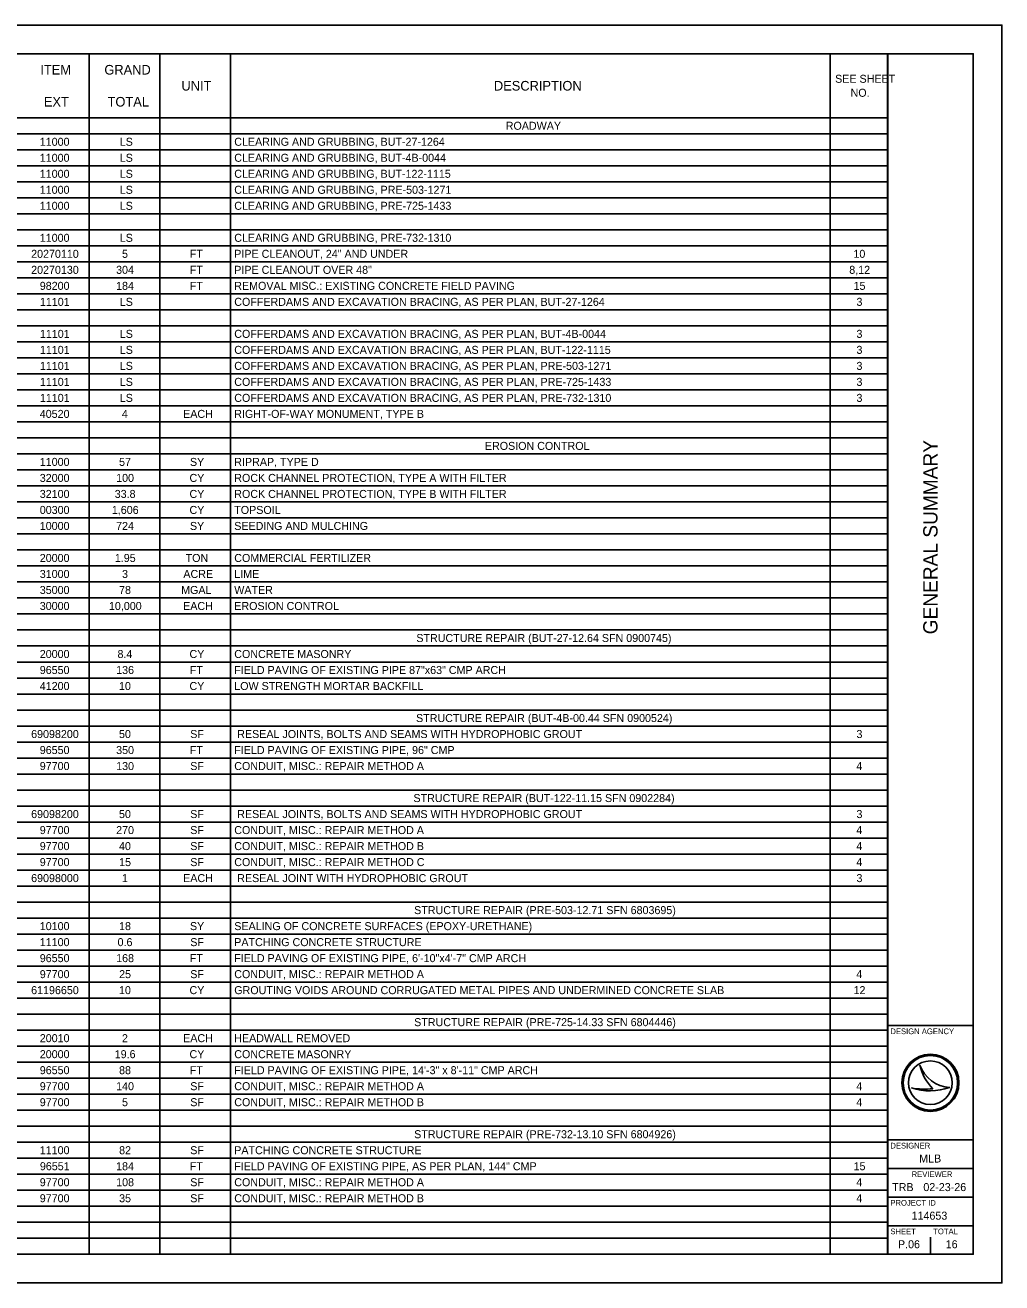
# Model space of a CAD drawing. Extents: x 0 to 34, y 0 to 22.
# Drawn here: x 16.92 to 34, y 0 to 22 of the extents above; entities that cross this region are included whole.
import ezdxf

# ---------------------------------------------------------------- set-up
doc = ezdxf.new("R2010")
doc.units = 0
for name, color, linetype in [('Default', 7, 'Continuous'), ('SH_Border', 7, 'Continuous'), ('SH_Cut_Line', 7, 'Continuous'), ('SH_Data', 7, 'Continuous')]:
    doc.layers.add(name, color=color, linetype=linetype)

msp = doc.modelspace()

# ---------------------------------------------------------------- linework, layer by layer
at = {"layer": 'Default'}
for p, q in [((1.5, 21.5), (32.004, 21.5)), ((18.036, 21.5), (18.036, 0.5)), ((19.272, 21.5), (19.272, 0.5)), ((20.507, 21.5), (20.507, 0.5)), ((30.999, 21.5), (30.999, 0.5)), ((32.004, 21.5), (32.004, 0.5)), ((1.5, 20.38), (32.004, 20.38)), ((1.5, 20.1), (32.004, 20.1)), ((1.5, 19.82), (32.004, 19.82)), ((1.5, 19.54), (32.004, 19.54)), ((1.5, 19.26), (32.004, 19.26)), ((1.5, 18.98), (32.004, 18.98)), ((1.5, 18.7), (32.004, 18.7)), ((1.5, 18.42), (32.004, 18.42)), ((1.5, 18.14), (32.004, 18.14)), ((1.5, 17.86), (32.004, 17.86)), ((1.5, 17.58), (32.004, 17.58)), ((1.5, 17.3), (32.004, 17.3)), ((1.5, 17.02), (32.004, 17.02)), ((1.5, 16.74), (32.004, 16.74)), ((1.5, 16.46), (32.004, 16.46)), ((1.5, 16.18), (32.004, 16.18)), ((1.5, 15.9), (32.004, 15.9)), ((1.5, 15.62), (32.004, 15.62)), ((1.5, 15.34), (32.004, 15.34)), ((1.5, 15.06), (32.004, 15.06)), ((1.5, 14.78), (32.004, 14.78)), ((1.5, 14.5), (32.004, 14.5)), ((1.5, 14.22), (32.004, 14.22)), ((1.5, 13.94), (32.004, 13.94)), ((1.5, 13.66), (32.004, 13.66)), ((1.5, 13.38), (32.004, 13.38)), ((1.5, 13.1), (32.004, 13.1)), ((1.5, 12.82), (32.004, 12.82)), ((1.5, 12.54), (32.004, 12.54)), ((1.5, 12.26), (32.004, 12.26)), ((1.5, 11.98), (32.004, 11.98)), ((1.5, 11.7), (32.004, 11.7)), ((1.5, 11.42), (32.004, 11.42)), ((1.5, 11.14), (32.004, 11.14)), ((1.5, 10.86), (32.004, 10.86)), ((1.5, 10.58), (32.004, 10.58)), ((1.5, 10.3), (32.004, 10.3)), ((1.5, 10.02), (32.004, 10.02)), ((1.5, 9.74), (32.004, 9.74)), ((1.5, 9.46), (32.004, 9.46)), ((1.5, 9.18), (32.004, 9.18)), ((1.5, 8.9), (32.004, 8.9)), ((1.5, 8.62), (32.004, 8.62)), ((1.5, 8.34), (32.004, 8.34)), ((1.5, 8.06), (32.004, 8.06)), ((1.5, 7.78), (32.004, 7.78)), ((1.5, 7.5), (32.004, 7.5)), ((1.5, 7.22), (32.004, 7.22)), ((1.5, 6.94), (32.004, 6.94)), ((1.5, 6.66), (32.004, 6.66)), ((1.5, 6.38), (32.004, 6.38)), ((1.5, 6.1), (32.004, 6.1)), ((1.5, 5.82), (32.004, 5.82)), ((1.5, 5.54), (32.004, 5.54)), ((1.5, 5.26), (32.004, 5.26)), ((1.5, 4.98), (32.004, 4.98)), ((1.5, 4.7), (32.004, 4.7)), ((1.5, 4.42), (32.004, 4.42)), ((1.5, 4.14), (32.004, 4.14)), ((1.5, 3.86), (32.004, 3.86)), ((1.5, 3.58), (32.004, 3.58)), ((1.5, 3.3), (32.004, 3.3)), ((1.5, 3.02), (32.004, 3.02)), ((1.5, 2.74), (32.004, 2.74)), ((1.5, 2.46), (32.004, 2.46)), ((1.5, 2.18), (32.004, 2.18)), ((1.5, 1.9), (32.004, 1.9)), ((1.5, 1.62), (32.004, 1.62)), ((1.5, 1.34), (32.004, 1.34)), ((1.5, 1.06), (32.004, 1.06)), ((1.5, 0.78), (32.004, 0.78)), ((1.5, 0.5), (32.004, 0.5))]:
    msp.add_line(p, q, dxfattribs=at)
at = {"layer": 'SH_Border'}
for p, q in [((32, 0.5), (32, 21.5)), ((32, 4.5), (33.5, 4.5)), ((32, 2.5), (33.5, 2.5)), ((32, 2), (33.5, 2)), ((32, 1.5), (33.5, 1.5)), ((32, 1), (33.5, 1))]:
    msp.add_line(p, q, dxfattribs=at)
msp.add_lwpolyline([(1.5, 21.5), (33.5, 21.5), (33.5, 0.5), (1.5, 0.5)], close=True, dxfattribs=at)
at = {"layer": 'SH_Cut_Line'}
msp.add_lwpolyline([(0, 0), (34, 0), (34, 22), (0, 22)], close=True, dxfattribs=at)
at = {"layer": 'SH_Data'}
for p, q in [((32.567, 3.81), (32.567, 3.81)), ((32.417, 3.41), (32.417, 3.41)), ((32.75, 3.5), (32.75, 3.5)), ((33.087, 3.419), (33.087, 3.419)), ((32.375, 0.675), (32.375, 0.675)), ((32.75, 0.5), (32.75, 0.8))]:
    msp.add_line(p, q, dxfattribs=at)
for radius in [0.5, 0.477, 0.477, 0.382]:
    msp.add_circle((32.75, 3.5), radius, dxfattribs=at)
for centre, radius, start, end in [((33.116, 3.998), 0.58, 198.9257, 198.9319), ((33.347, 3.97), 0.796, 191.6379, 191.6421), ((33.116, 3.998), 0.58, 198.9319, 267.1657), ((33.347, 3.97), 0.796, 191.6421, 226.0947), ((32.739, 4.37), 1.013, 251.4576, 290.0832), ((32.648, 4.654), 1.266, 259.4964, 259.4995), ((32.739, 4.37), 1.013, 251.4527, 251.4576), ((32.648, 4.654), 1.266, 259.4995, 276.6672)]:
    msp.add_arc(centre, radius, start, end, dxfattribs=at)

# ---------------------------------------------------------------- texts
at = {"layer": 'Default'}
for s, height, p in [('ITEM', 0.168, (17.181, 21.136)), ('GRAND', 0.168, (18.301, 21.136)), ('SEE SHEET ', 0.14, (31.084, 20.992)), ('UNIT', 0.168, (19.649, 20.856)), ('DESCRIPTION', 0.168, (25.115, 20.856)), ('EXT', 0.168, (17.242, 20.576)), ('TOTAL', 0.168, (18.357, 20.576)), ('NO.', 0.14, (31.354, 20.747)), ('ROADWAY', 0.14, (25.322, 20.17)), ('11000', 0.14, (17.171, 19.89)), ('LS', 0.14, (18.57, 19.89)), ('CLEARING AND GRUBBING, BUT-27-1264', 0.14, (20.573, 19.89)), ('11000', 0.14, (17.171, 19.61)), ('LS', 0.14, (18.57, 19.61)), ('CLEARING AND GRUBBING, BUT-4B-0044', 0.14, (20.573, 19.61)), ('11000', 0.14, (17.171, 19.33)), ('LS', 0.14, (18.57, 19.33)), ('CLEARING AND GRUBBING, BUT-122-1115', 0.14, (20.573, 19.33)), ('11000', 0.14, (17.171, 19.05)), ('LS', 0.14, (18.57, 19.05)), ('CLEARING AND GRUBBING, PRE-503-1271', 0.14, (20.573, 19.05)), ('11000', 0.14, (17.171, 18.77)), ('LS', 0.14, (18.57, 18.77)), ('CLEARING AND GRUBBING, PRE-725-1433', 0.14, (20.573, 18.77)), ('11000', 0.14, (17.171, 18.21)), ('LS', 0.14, (18.57, 18.21)), ('CLEARING AND GRUBBING, PRE-732-1310', 0.14, (20.573, 18.21)), ('20270110', 0.14, (17.02, 17.93)), ('5', 0.14, (18.61, 17.93)), ('FT', 0.14, (19.796, 17.93)), ('PIPE CLEANOUT, 24" AND UNDER', 0.14, (20.573, 17.93)), ('10', 0.14, (31.404, 17.93)), ('20270130', 0.14, (17.02, 17.65)), ('304', 0.14, (18.506, 17.65)), ('FT', 0.14, (19.796, 17.65)), ('PIPE CLEANOUT OVER 48"', 0.14, (20.573, 17.65)), ('8,12', 0.14, (31.331, 17.65)), ('98200', 0.14, (17.171, 17.37)), ('184', 0.14, (18.506, 17.37)), ('FT', 0.14, (19.796, 17.37)), ('REMOVAL MISC.: EXISTING CONCRETE FIELD PAVING', 0.14, (20.573, 17.37)), ('15', 0.14, (31.406, 17.37)), ('11101', 0.14, (17.173, 17.09)), ('LS', 0.14, (18.57, 17.09)), ('COFFERDAMS AND EXCAVATION BRACING, AS PER PLAN, BUT-27-1264', 0.14, (20.573, 17.09)), ('3', 0.14, (31.457, 17.09)), ('11101', 0.14, (17.173, 16.53)), ('LS', 0.14, (18.57, 16.53)), ('COFFERDAMS AND EXCAVATION BRACING, AS PER PLAN, BUT-4B-0044', 0.14, (20.573, 16.53)), ('3', 0.14, (31.457, 16.53)), ('11101', 0.14, (17.173, 16.25)), ('LS', 0.14, (18.57, 16.25)), ('COFFERDAMS AND EXCAVATION BRACING, AS PER PLAN, BUT-122-1115', 0.14, (20.573, 16.25)), ('3', 0.14, (31.457, 16.25)), ('11101', 0.14, (17.173, 15.97)), ('LS', 0.14, (18.57, 15.97)), ('COFFERDAMS AND EXCAVATION BRACING, AS PER PLAN, PRE-503-1271', 0.14, (20.573, 15.97)), ('3', 0.14, (31.457, 15.97)), ('11101', 0.14, (17.173, 15.69)), ('LS', 0.14, (18.57, 15.69)), ('COFFERDAMS AND EXCAVATION BRACING, AS PER PLAN, PRE-725-1433', 0.14, (20.573, 15.69)), ('3', 0.14, (31.457, 15.69)), ('11101', 0.14, (17.173, 15.41)), ('LS', 0.14, (18.57, 15.41)), ('COFFERDAMS AND EXCAVATION BRACING, AS PER PLAN, PRE-732-1310', 0.14, (20.573, 15.41)), ('3', 0.14, (31.457, 15.41)), ('40520', 0.14, (17.171, 15.13)), ('4', 0.14, (18.607, 15.13)), ('EACH', 0.14, (19.679, 15.13)), ('RIGHT-OF-WAY MONUMENT, TYPE B', 0.14, (20.573, 15.13)), ('EROSION CONTROL', 0.14, (24.957, 14.57)), ('11000', 0.14, (17.171, 14.29)), ('57', 0.14, (18.558, 14.29)), ('SY', 0.14, (19.798, 14.29)), ('RIPRAP, TYPE D', 0.14, (20.573, 14.29)), ('32000', 0.14, (17.171, 14.01)), ('100', 0.14, (18.507, 14.01)), ('CY', 0.14, (19.79, 14.01)), ('ROCK CHANNEL PROTECTION, TYPE A WITH FILTER', 0.14, (20.573, 14.01)), ('32100', 0.14, (17.171, 13.73)), ('33.8', 0.14, (18.482, 13.73)), ('CY', 0.14, (19.79, 13.73)), ('ROCK CHANNEL PROTECTION, TYPE B WITH FILTER', 0.14, (20.573, 13.73)), ('00300', 0.14, (17.171, 13.45)), ('1,606', 0.14, (18.432, 13.45)), ('CY', 0.14, (19.79, 13.45)), ('TOPSOIL', 0.14, (20.573, 13.45)), ('10000', 0.14, (17.171, 13.17)), ('724', 0.14, (18.506, 13.17)), ('SY', 0.14, (19.798, 13.17)), ('SEEDING AND MULCHING', 0.14, (20.573, 13.17)), ('20000', 0.14, (17.171, 12.61)), ('1.95', 0.14, (18.484, 12.61)), ('TON', 0.14, (19.722, 12.61)), ('COMMERCIAL FERTILIZER', 0.14, (20.573, 12.61)), ('31000', 0.14, (17.171, 12.33)), ('3', 0.14, (18.61, 12.33)), ('ACRE', 0.14, (19.683, 12.33)), ('LIME', 0.14, (20.573, 12.33)), ('35000', 0.14, (17.171, 12.05)), ('78', 0.14, (18.558, 12.05)), ('MGAL', 0.14, (19.644, 12.05)), ('WATER', 0.14, (20.573, 12.05)), ('30000', 0.14, (17.171, 11.77)), ('10,000', 0.14, (18.381, 11.77)), ('EACH', 0.14, (19.679, 11.77)), ('EROSION CONTROL', 0.14, (20.573, 11.77)), ('STRUCTURE REPAIR (BUT-27-12.64 SFN 0900745)', 0.14, (23.758, 11.21)), ('20000', 0.14, (17.171, 10.93)), ('8.4', 0.14, (18.531, 10.93)), ('CY', 0.14, (19.79, 10.93)), ('CONCRETE MASONRY', 0.14, (20.573, 10.93)), ('96550', 0.14, (17.171, 10.65)), ('136', 0.14, (18.507, 10.65)), ('FT', 0.14, (19.796, 10.65)), ('FIELD PAVING OF EXISTING PIPE 87"x63" CMP ARCH', 0.14, (20.573, 10.65)), ('41200', 0.14, (17.171, 10.37)), ('10', 0.14, (18.557, 10.37)), ('CY', 0.14, (19.79, 10.37)), ('LOW STRENGTH MORTAR BACKFILL', 0.14, (20.573, 10.37)), ('STRUCTURE REPAIR (BUT-4B-00.44 SFN 0900524)', 0.14, (23.753, 9.81)), ('69098200', 0.14, (17.02, 9.53)), ('50', 0.14, (18.557, 9.53)), ('SF', 0.14, (19.803, 9.53)), (' RESEAL JOINTS, BOLTS AND SEAMS WITH HYDROPHOBIC GROUT', 0.14, (20.573, 9.53)), ('3', 0.14, (31.457, 9.53)), ('96550', 0.14, (17.171, 9.25)), ('350', 0.14, (18.507, 9.25)), ('FT', 0.14, (19.796, 9.25)), ('FIELD PAVING OF EXISTING PIPE, 96" CMP', 0.14, (20.573, 9.25)), ('97700', 0.14, (17.171, 8.97)), ('130', 0.14, (18.507, 8.97)), ('SF', 0.14, (19.803, 8.97)), ('CONDUIT, MISC.: REPAIR METHOD A', 0.14, (20.573, 8.97)), ('4', 0.14, (31.454, 8.97)), ('STRUCTURE REPAIR (BUT-122-11.15 SFN 0902284)', 0.14, (23.708, 8.41)), ('69098200', 0.14, (17.02, 8.13)), ('50', 0.14, (18.557, 8.13)), ('SF', 0.14, (19.803, 8.13)), (' RESEAL JOINTS, BOLTS AND SEAMS WITH HYDROPHOBIC GROUT', 0.14, (20.573, 8.13)), ('3', 0.14, (31.457, 8.13)), ('97700', 0.14, (17.171, 7.85)), ('270', 0.14, (18.507, 7.85)), ('SF', 0.14, (19.803, 7.85)), ('CONDUIT, MISC.: REPAIR METHOD A', 0.14, (20.573, 7.85)), ('4', 0.14, (31.454, 7.85)), ('97700', 0.14, (17.171, 7.57)), ('40', 0.14, (18.557, 7.57)), ('SF', 0.14, (19.803, 7.57)), ('CONDUIT, MISC.: REPAIR METHOD B', 0.14, (20.573, 7.57)), ('4', 0.14, (31.454, 7.57)), ('97700', 0.14, (17.171, 7.29)), ('15', 0.14, (18.559, 7.29)), ('SF', 0.14, (19.803, 7.29)), ('CONDUIT, MISC.: REPAIR METHOD C', 0.14, (20.573, 7.29)), ('4', 0.14, (31.454, 7.29)), ('69098000', 0.14, (17.02, 7.01)), ('1', 0.14, (18.609, 7.01)), ('EACH', 0.14, (19.679, 7.01)), (' RESEAL JOINT WITH HYDROPHOBIC GROUT', 0.14, (20.573, 7.01)), ('3', 0.14, (31.457, 7.01)), ('STRUCTURE REPAIR (PRE-503-12.71 SFN 6803695)', 0.14, (23.72, 6.45)), ('10100', 0.14, (17.171, 6.17)), ('18', 0.14, (18.558, 6.17)), ('SY', 0.14, (19.798, 6.17)), ('SEALING OF CONCRETE SURFACES (EPOXY-URETHANE)', 0.14, (20.573, 6.17)), ('11100', 0.14, (17.171, 5.89)), ('0.6', 0.14, (18.532, 5.89)), ('SF', 0.14, (19.803, 5.89)), ('PATCHING CONCRETE STRUCTURE', 0.14, (20.573, 5.89)), ('96550', 0.14, (17.171, 5.61)), ('168', 0.14, (18.507, 5.61)), ('FT', 0.14, (19.796, 5.61)), ('FIELD PAVING OF EXISTING PIPE, 6\'-10"x4\'-7" CMP ARCH', 0.14, (20.573, 5.61)), ('97700', 0.14, (17.171, 5.33)), ('25', 0.14, (18.559, 5.33)), ('SF', 0.14, (19.803, 5.33)), ('CONDUIT, MISC.: REPAIR METHOD A', 0.14, (20.573, 5.33)), ('4', 0.14, (31.454, 5.33)), ('61196650', 0.14, (17.02, 5.05)), ('10', 0.14, (18.557, 5.05)), ('CY', 0.14, (19.79, 5.05)), ('GROUTING VOIDS AROUND CORRUGATED METAL PIPES AND UNDERMINED CONCRETE SLAB', 0.14, (20.573, 5.05)), ('12', 0.14, (31.406, 5.05)), ('STRUCTURE REPAIR (PRE-725-14.33 SFN 6804446)', 0.14, (23.72, 4.49)), ('20010', 0.14, (17.171, 4.21)), ('2', 0.14, (18.609, 4.21)), ('EACH', 0.14, (19.679, 4.21)), ('HEADWALL REMOVED', 0.14, (20.573, 4.21)), ('20000', 0.14, (17.171, 3.93)), ('19.6', 0.14, (18.482, 3.93)), ('CY', 0.14, (19.79, 3.93)), ('CONCRETE MASONRY', 0.14, (20.573, 3.93)), ('96550', 0.14, (17.171, 3.65)), ('88', 0.14, (18.558, 3.65)), ('FT', 0.14, (19.796, 3.65)), ('FIELD PAVING OF EXISTING PIPE, 14\'-3" x 8\'-11" CMP ARCH', 0.14, (20.573, 3.65)), ('97700', 0.14, (17.171, 3.37)), ('140', 0.14, (18.507, 3.37)), ('SF', 0.14, (19.803, 3.37)), ('CONDUIT, MISC.: REPAIR METHOD A', 0.14, (20.573, 3.37)), ('4', 0.14, (31.454, 3.37)), ('97700', 0.14, (17.171, 3.09)), ('5', 0.14, (18.61, 3.09)), ('SF', 0.14, (19.803, 3.09)), ('CONDUIT, MISC.: REPAIR METHOD B', 0.14, (20.573, 3.09)), ('4', 0.14, (31.454, 3.09)), ('STRUCTURE REPAIR (PRE-732-13.10 SFN 6804926)', 0.14, (23.72, 2.53)), ('11100', 0.14, (17.171, 2.25)), ('82', 0.14, (18.559, 2.25)), ('SF', 0.14, (19.803, 2.25)), ('PATCHING CONCRETE STRUCTURE', 0.14, (20.573, 2.25)), ('96551', 0.14, (17.173, 1.97)), ('184', 0.14, (18.506, 1.97)), ('FT', 0.14, (19.796, 1.97)), ('FIELD PAVING OF EXISTING PIPE, AS PER PLAN, 144" CMP', 0.14, (20.573, 1.97)), ('15', 0.14, (31.406, 1.97)), ('97700', 0.14, (17.171, 1.69)), ('108', 0.14, (18.507, 1.69)), ('SF', 0.14, (19.803, 1.69)), ('CONDUIT, MISC.: REPAIR METHOD A', 0.14, (20.573, 1.69)), ('4', 0.14, (31.454, 1.69)), ('97700', 0.14, (17.171, 1.41)), ('35', 0.14, (18.559, 1.41)), ('SF', 0.14, (19.803, 1.41)), ('CONDUIT, MISC.: REPAIR METHOD B', 0.14, (20.573, 1.41)), ('4', 0.14, (31.454, 1.41))]:
    msp.add_text(s, height=height, dxfattribs=at).set_placement(p)
at = {"layer": 'SH_Data'}
msp.add_text('GENERAL SUMMARY', height=0.25, rotation=90, dxfattribs=at).set_placement((32.875, 11.344))
for s, height, p in [('DESIGN AGENCY', 0.1, (32.05, 4.35)), ('DESIGNER', 0.1, (32.05, 2.35)), ('MLB', 0.14, (32.554, 2.105)), ('REVIEWER', 0.1, (32.422, 1.85)), ('TRB', 0.14, (32.081, 1.605)), ('02-23-26', 0.14, (32.627, 1.605)), ('PROJECT ID', 0.1, (32.05, 1.35)), ('114653', 0.14, (32.421, 1.105)), ('SHEET', 0.1, (32.05, 0.85)), ('TOTAL', 0.1, (32.8, 0.85)), ('P.06', 0.14, (32.183, 0.605)), ('16', 0.14, (33.018, 0.605))]:
    msp.add_text(s, height=height, dxfattribs=at).set_placement(p)

doc.saveas('drawing.dxf')
